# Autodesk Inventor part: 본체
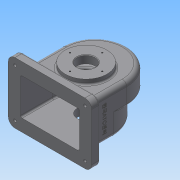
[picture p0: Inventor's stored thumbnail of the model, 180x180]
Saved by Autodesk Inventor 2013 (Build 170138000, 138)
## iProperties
Created: 2017-11
Part Number: 본체
Material: 일반
Document SubType Name: Modeling
Designer: Administrator
Density: 1 g/cm^3
Author: Administrator
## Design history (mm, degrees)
sketch "스케치4"
  geometry: L1 (-75, -65)-(75, -65); L2 (75, -65)-(75, -80); L3 (75, -80)-(-75, -80); L4 (-75, -80)-(-75, -65); 2 further points
  constraints: 8 end point, 2 parallel, 1 horizontal, 1 midpoint, 1 perpendicular, 1 vertical alignment
  dimensions: "d2" = 80 distance from line of L3 point (0, 0); "d3" = 150 distance of L2.end L3.end; "d4" = 15 distance of L1.end L2.end
extrude "돌출1" new body sketch "스케치4" stored distance "d5" = 110; taper "d6" = 0 deg
fillet "모깎기1" dims "d10" = 12
sketch "스케치6"
  geometry: L1 (-58, 0)-(-58, -65); L2 (58, 0)-(58, -65); L3 (-63, -65)-(63, -65) reference; A1 r 58 centre (0, 0) between (-58, 0) and (58, 0); 1 further point
  constraints: 4 end point, 2 point on circle, 2 point on line, 2 tangent, 1 centre point, 1 coincident, 1 parallel, 1 vertical
  dimensions: "d11" = 116 diameter of A1
extrude "돌출2" join sketch "스케치6" distance "d12" = 38; taper "d13" = 0 deg
sketch "스케치7"
  geometry: L1 (58, 0)-(58, -65) reference; L2 (-58, -65)-(-58, 0) reference; L3 (58, -65)-(-58, -65) reference; L4 (-63, -80)-(63, -80) reference; A1 r 58 centre (0, 0) between (58, 0) and (-58, 0) reference; A2 r 58 centre (0, -23) between (58, -23) and (-58, -23)
  constraints: 2 point on circle, 2 point on line, 1 centre point, 1 vertical alignment
  dimensions: "d14" = 116 diameter of A2; "d15" = 57 distance from line of L4 A2.centre
extrude "돌출3" join sketch "스케치7" distance "d16" = 38; taper "d17" = 0 deg
feature "쉘1" dims "d27" = 5
sketch "스케치10"
  geometry: L1 (116, 17)-(116, 83) reference; L2 (10, 17)-(116, 17) reference; L3 (10, 83)-(10, 17) reference; L4 (116, 83)-(10, 83) reference; L5 (0, 0)-(126, 0) reference; L6 (133, 93)-(133, 7) reference; L7 (126, 100)-(0, 100) reference; L8 (-7, 7)-(-7, 93) reference; A1 r 7 centre (0, 7) between (-7, 7) and (0, 0) reference; A2 r 7 centre (126, 7) between (126, 0) and (133, 7) reference; A3 r 7 centre (126, 93) between (133, 93) and (126, 100) reference; A4 r 7 centre (0, 93) between (0, 100) and (-7, 93) reference; 1 further point
extrude "돌출4" join sketch "스케치10" stored distance "d28" = 28; taper "d29" = 0 deg
sketch "스케치11"
  geometry: L1 (-63, -80)-(63, -80) reference; C1 r 31 at (0, -15); A1 r 58 centre (0, -23) between (58, -23) and (-58, -23) reference; 1 further point
  constraints: 1 centre point, 1 vertical alignment
  dimensions: "d33" = 62 diameter of C1; "d34" = 65 distance from line of L1 C1.centre
sketch "스케치12"
  geometry: L1 (-63, -80)-(63, -80) reference; C1 r 37.5 at (0, -15); A1 r 58 centre (0, 0) between (58, 0) and (-58, 0) reference
  constraints: 1 centre point, 1 vertical alignment
  dimensions: "d31" = 75 diameter of C1; "d32" = 65 distance from line of L1 C1.centre
extrude "돌출5" join sketch "스케치11" distance "d35" = 10; taper "d36" = 0 deg
extrude "돌출6" join sketch "스케치12" distance "d37" = 9; taper "d38" = 0 deg
sketch "스케치13"
  geometry: C1 r 31 at (0, 0) reference; C2 r 16 at (0, 0); 1 further point
  constraints: 1 centre point, 1 coincident
  dimensions: "d39" = 32 diameter of C2
extrude "돌출7" cut sketch "스케치13" stored distance "d40" = 9; taper "d41" = 0 deg
node "작업 평면1"
sketch "스케치14"
  geometry: L1 (-12, 12)-(-12, 98) reference; L2 (121, 93)-(5, 93) reference; C1 r 6 at (63, 74); 1 further point
  constraints: 1 centre point
  dimensions: "d45" = 12 diameter of C1; "d46" = 75 distance from line of L1 C1.centre; "d47" = 19 distance from line of L2 C1.centre
extrude "돌출8" join sketch "스케치14" stored distance "d48" = 9; taper "d49" = 0 deg
hole "구멍1" diameter "d52" = 4.459; stored, may be unused: countersink angle "d56" = 90 deg, drill point angle "d58" = 118 deg; dims "d50" = 10, "d51" = 10, "d53" = 6, "d54" = 4, "d55" = 2, "d57" = 8
sketch "스케치15"
  geometry: A1 r 12 centre (0, 98) between (0, 110) and (-12, 98) reference; A2 r 12 centre (0, 12) between (-12, 12) and (0, 0) reference; A3 r 12 centre (126, 12) between (126, 0) and (138, 12) reference; A4 r 12 centre (126, 98) between (138, 98) and (126, 110) reference; 5 further points
  constraints: 4 coincident
hole "구멍2" sketch "스케치15" at (0, 12), (0, 98), (126, 98), (126, 12) diameter "d62" = 5; stored, may be unused: countersink angle "d66" = 90 deg, drill point angle "d68" = 118 deg; dims "d63" = 6, "d64" = 12, "d65" = 5, "d67" = 8
chamfer "모따기1" distance "d69" = 1; stored, may be unused: second distance "d70" = 2, angle "d71" = 45 deg
fillet "모깎기3" dims "d73" = 8
fillet "모깎기4" dims "d74" = 3
fillet "모깎기5" dims "d75" = 3
sketch "스케치16" dims "d40" = 9, "d41" = 0
  geometry: L1 (-8, 62)-(-8, 0) reference; L2 (-13, -18)-(73, -18) reference; 2 further points
  constraints: 1 other
  dimensions: "d77" = 38 distance from line of L1 point (30, 22); "d78" = 40 distance from line of point (30, 22) L2
feature "엠보싱1" sketch "스케치16" dims "d2" = 80, "d3" = 150, "d4" = 15, "d79" = 0.5, "d80" = 0
fillet "모깎기7" dims "d81" = 3
sketch "스케치17"
  geometry: C1 r 37.5 at (0, 0) reference; 2 further points
  constraints: 1 vertical alignment
  dimensions: "d82" = 29 distance of point (0, 29) C1.centre
hole "구멍3" sketch "스케치17" at (0, 29) diameter "d83" = 2.459; stored, may be unused: countersink angle "d87" = 90 deg, drill point angle "d89" = 118 deg; dims "d84" = 6, "d85" = 12, "d86" = 5, "d88" = 8
sketch "스케치18"
  geometry: C1 r 31 at (0, 0) reference; 2 further points
  constraints: 1 vertical alignment
  dimensions: "d93" = 26 distance of C1.centre point (0, 26)
hole "구멍4" sketch "스케치18" at (0, 26) diameter "d94" = 2.459; stored, may be unused: countersink angle "d98" = 90 deg, drill point angle "d100" = 118 deg; dims "d95" = 6, "d96" = 12, "d97" = 5, "d99" = 8
node "솔리드1"
pattern_circular "원형 패턴1" dims angle "d91" = 360 deg
pattern_circular "원형 패턴2" dims angle "d102" = 360 deg
other parameters: "d42" = -144
